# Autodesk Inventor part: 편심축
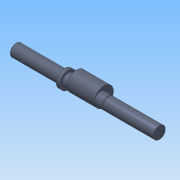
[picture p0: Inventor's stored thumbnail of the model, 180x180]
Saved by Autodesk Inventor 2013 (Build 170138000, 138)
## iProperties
Manager: 한국ATC센터
Company: 한국ATC센터
Created: 2014-10
Part Number: 편심축
Document SubType Name: Modeling
Designer: 한국ATC센터
Density: 7.86 g/cm^3
Material: 강, 연강
Mass: 1459.35 g
Surface Area: 294.403 cm^2
Volume: 185.668 cm^3
Author: KYOUNG IL JANG
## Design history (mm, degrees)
sketch "스케치1"
  geometry: L1 (-147, 0)-(147, 0); L2 (-147, 0)-(-147, 12.5); L3 (-147, 12.5)-(-47, 12.5); L4 (-47, 12.5)-(-47, 17.5); L5 (-47, 17.5)-(-40, 17.5); L6 (-40, 17.5)-(-40, 12.5); L7 (-40, 12.5)-(41.65, 12.5); L8 (41.65, 12.5)-(41.65, 11.95); L9 (41.65, 11.95)-(43, 11.95); L10 (43, 11.95)-(43, 12.5); L11 (43, 12.5)-(147, 12.5); L12 (147, 12.5)-(147, 0); L13 (114, 12.5)-(114, 9.1); L14 (114, 9.1)-(139, 9.1); L15 (139, 9.1)-(139, 12.5); L16 (122, -12.5)-(124.5, -12.5); L17 (124.5, -12.5)-(122, -10); L18 (122, -10)-(122, -12.5); L19 (-114, 12.5)-(-114, 9.1); L20 (-114, 9.1)-(-139, 9.1); L21 (-139, 9.1)-(-139, 12.5); L22 (-122, -12.5)-(-122, -10); L23 (-122, -10)-(-119.5, -12.5); L24 (-119.5, -12.5)-(-122, -12.5); 2 further points
  constraints: 48 end point, 11 parallel, 8 perpendicular, 5 collinear, 4 point on line, 1 coincident, 1 horizontal, 1 midpoint, 1 vertical
  dimensions: "d0" = 294 distance of L1.start L1.end (derived); "d1" = 25 diameter of L3 L1; "d2" = 35 diameter of L5 L1; "d3" = 100 distance of L2.end L3.end; "d4" = 187 distance between parallel lines of L12 L6; "d6" = 1.35 distance of L8.end L9.end; "d7" = 23.9 diameter of L9 L1; "d8" = 3.4 distance between parallel lines of L14 L11; "d9" = 8 distance between parallel lines of L15 L12; "d10" = 25 distance of L13.end L14.end; "d11" = 25 diameter of L16 L1 (= d1); "d12" = 25 distance from line of L12 L16.start; "d13" = 45 deg angle of L17 L18; "d14" = 5 diameter of L16.end L18; "d27" = 104 distance between parallel lines of L10 L12; "d32" = 7 distance of L4.end L5.end; "d33" = 8 distance between parallel lines of L2 L21; "d34" = 25 distance between parallel lines of L21 L19; "d35" = 3.4 distance between parallel lines of L3 L20; "d36" = 25 distance from line of L22.start L2; "d37" = 5 diameter of L23.end L22
revolve "회전1" stored, may be unused: angle "d15" = 90 deg
revolve "회전2" stored, may be unused: angle "d16" = 90 deg
revolve "회전3" stored, may be unused: angle "d38" = 90 deg
extrude "돌출1" cut sketch "스케치1" stored distance "d17" = 8; taper "d18" = 0 deg
fillet "모깎기1" dims "d19" = 4
node "작업 평면1"
sketch "스케치2"
  geometry: C1 r 12.5 at (0, 0) reference; C2 r 19.5 at (0, 7); 1 further point
  constraints: 1 centre point, 1 tangent, 1 vertical alignment
  dimensions: "d21" = 7 distance of point (0, 0) C2.centre; "d30" = 39 diameter of C2 (derived)
extrude "돌출2" join sketch "스케치2" distance "d22" = 56; taper "d23" = 0 deg
chamfer "모따기1" distance "d24" = 1; stored, may be unused: second distance "d25" = 2, angle "d26" = 45 deg
node "솔리드1"
